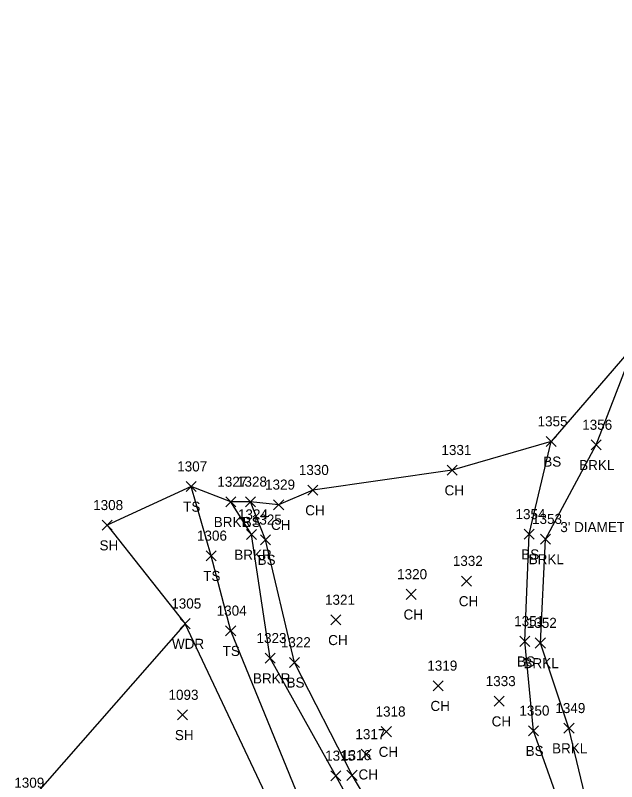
# Model space of a CAD drawing. Extents: x 1651685 to 1653558, y 889533 to 891085.
# Drawn here: x 1652558.4 to 1652677.7, y 890337.8 to 890489.8 of the extents above; entities that cross this region are included whole.
import ezdxf

# ---------------------------------------------------------------- set-up
doc = ezdxf.new("R2010")
doc.units = 0
for name, color, linetype in [('L_A', 7, 'Continuous'), ('L_I', 7, 'Continuous'), ('L_TIC', 7, 'Continuous'), ('LAWA', 7, 'Continuous'), ('LAWE', 7, 'Continuous'), ('LELB', 7, 'Continuous'), ('LSOGP', 7, 'Continuous'), ('U_C', 7, 'Continuous')]:
    doc.layers.add(name, color=color, linetype=linetype)

msp = doc.modelspace()

# ---------------------------------------------------------------- linework, layer by layer
at = {"layer": 'L_TIC'}
for points in [[(1652663.7, 890404.27), (1652665.7, 890406.27)], [(1652665.7, 890404.27), (1652663.7, 890406.27)], [(1652672.62, 890403.58), (1652674.62, 890405.58)], [(1652674.62, 890403.58), (1652672.62, 890405.58)], [(1652644.06, 890398.57), (1652646.06, 890400.57)], [(1652646.06, 890398.57), (1652644.06, 890400.57)], [(1652592.27, 890395.32), (1652594.27, 890397.32)], [(1652594.27, 890395.32), (1652592.27, 890397.32)], [(1652616.41, 890394.61), (1652618.41, 890396.61)], [(1652618.41, 890394.61), (1652616.41, 890396.61)], [(1652600.16, 890392.28), (1652602.16, 890394.28)], [(1652602.16, 890392.28), (1652600.16, 890394.28)], [(1652604.05, 890392.3), (1652606.05, 890394.3)], [(1652606.05, 890392.3), (1652604.05, 890394.3)], [(1652609.63, 890391.71), (1652611.63, 890393.71)], [(1652611.63, 890391.71), (1652609.63, 890393.71)], [(1652575.59, 890387.65), (1652577.59, 890389.65)], [(1652577.59, 890387.65), (1652575.59, 890389.65)], [(1652604.24, 890385.79), (1652606.24, 890387.79)], [(1652606.24, 890385.79), (1652604.24, 890387.79)], [(1652659.32, 890385.85), (1652661.32, 890387.85)], [(1652661.32, 890385.85), (1652659.32, 890387.85)], [(1652607, 890384.77), (1652609, 890386.77)], [(1652609, 890384.77), (1652607, 890386.77)], [(1652662.6, 890384.9), (1652664.6, 890386.9)], [(1652664.6, 890384.9), (1652662.6, 890386.9)], [(1652596.25, 890381.58), (1652598.25, 890383.58)], [(1652598.25, 890381.58), (1652596.25, 890383.58)], [(1652646.89, 890376.57), (1652648.89, 890378.57)], [(1652648.89, 890376.57), (1652646.89, 890378.57)], [(1652635.92, 890373.93), (1652637.92, 890375.93)], [(1652637.92, 890373.93), (1652635.92, 890375.93)], [(1652620.96, 890368.86), (1652622.96, 890370.86)], [(1652622.96, 890368.86), (1652620.96, 890370.86)], [(1652591.1, 890368.11), (1652593.1, 890370.11)], [(1652593.1, 890368.11), (1652591.1, 890370.11)], [(1652600.11, 890366.7), (1652602.11, 890368.7)], [(1652602.11, 890366.7), (1652600.11, 890368.7)], [(1652658.49, 890364.61), (1652660.49, 890366.61)], [(1652660.49, 890364.61), (1652658.49, 890366.61)], [(1652661.56, 890364.27), (1652663.56, 890366.27)], [(1652663.56, 890364.27), (1652661.56, 890366.27)], [(1652607.93, 890361.26), (1652609.93, 890363.26)], [(1652609.93, 890361.26), (1652607.93, 890363.26)], [(1652612.75, 890360.43), (1652614.75, 890362.43)], [(1652614.75, 890360.43), (1652612.75, 890362.43)], [(1652641.26, 890355.79), (1652643.26, 890357.79)], [(1652643.26, 890355.79), (1652641.26, 890357.79)], [(1652653.41, 890352.72), (1652655.41, 890354.72)], [(1652655.41, 890352.72), (1652653.41, 890354.72)], [(1652590.54, 890350), (1652592.54, 890352)], [(1652592.54, 890350), (1652590.54, 890352)], [(1652667.24, 890347.37), (1652669.24, 890349.37)], [(1652669.24, 890347.37), (1652667.24, 890349.37)], [(1652630.99, 890346.68), (1652632.99, 890348.68)], [(1652632.99, 890346.68), (1652630.99, 890348.68)], [(1652660.19, 890346.87), (1652662.19, 890348.87)], [(1652662.19, 890346.87), (1652660.19, 890348.87)], [(1652626.99, 890342.19), (1652628.99, 890344.19)], [(1652628.99, 890342.19), (1652626.99, 890344.19)], [(1652620.98, 890337.92), (1652622.98, 890339.92)], [(1652622.98, 890337.92), (1652620.98, 890339.92)], [(1652624.19, 890338.02), (1652626.19, 890340.02)], [(1652626.19, 890338.02), (1652624.19, 890340.02)]]:
    msp.add_lwpolyline(points, dxfattribs=at)
at = {"layer": 'LAWA'}
msp.add_lwpolyline([(1652634, 890223.2), (1652645.93, 890237.94), (1652644.79, 890250.03), (1652631.58, 890279.12), (1652627.58, 890295.01), (1652615.37, 890319.79), (1652592.1, 890369.11), (1652560.95, 890333.56)], dxfattribs=at)
at = {"layer": 'LAWE'}
for points in [[(1652673.4, 890326.85), (1652668.24, 890348.37), (1652662.56, 890365.27), (1652663.6, 890385.9), (1652673.62, 890404.58), (1652681.39, 890424.61)], [(1652673.03, 890269.95), (1652662.28, 890278.74), (1652652.26, 890288.07), (1652634.07, 890316.8), (1652621.98, 890338.92), (1652608.93, 890362.26), (1652605.24, 890386.79), (1652601.16, 890393.28)]]:
    msp.add_lwpolyline(points, dxfattribs=at)
at = {"layer": 'LELB'}
for points in [[(1652670.46, 890321.8), (1652661.19, 890347.87), (1652659.49, 890365.61), (1652660.32, 890386.85), (1652664.7, 890405.27)], [(1652650.54, 890241.16), (1652659.11, 890253.33), (1652656.31, 890268.79), (1652646.77, 890284.89), (1652637.95, 890297.47), (1652620.82, 890319.5), (1652601.11, 890367.7), (1652597.25, 890382.58), (1652593.27, 890396.32)], [(1652655.64, 890289.65), (1652637.44, 890318.42), (1652625.19, 890339.02), (1652613.75, 890361.43), (1652608, 890385.77), (1652605.05, 890393.3)]]:
    msp.add_lwpolyline(points, dxfattribs=at)
at = {"layer": 'LSOGP'}
msp.add_lwpolyline([(1652755.23, 890514.52), (1652738.16, 890487.37), (1652752.74, 890483.86), (1652743.13, 890454.81), (1652739.83, 890456.16), (1652737.58, 890449.68), (1652732.33, 890451.47), (1652726.97, 890443.32), (1652732.31, 890441.75), (1652729.8, 890435.09), (1652722.88, 890415.78), (1652698.47, 890424.18), (1652681.39, 890424.6), (1652664.7, 890405.27), (1652645.06, 890399.57), (1652617.41, 890395.61), (1652610.62, 890392.71), (1652605.05, 890393.3), (1652601.16, 890393.28), (1652593.27, 890396.32), (1652576.59, 890388.65), (1652592.1, 890369.11), (1652560.95, 890333.56)], dxfattribs=at)

# ---------------------------------------------------------------- texts
at = {"layer": 'L_A'}
for s, p in [('BS', (1652663.14, 890400.27)), ('BRKL', (1652670.26, 890399.58)), ('CH', (1652643.55, 890394.57)), ('TS', (1652591.68, 890391.32)), ('CH', (1652615.9, 890390.61)), ('BRKR', (1652597.75, 890388.28)), ('BS', (1652603.49, 890388.3)), ('CH', (1652609.11, 890387.71)), ('SH', (1652575.08, 890383.65)), ('BRKR', (1652601.83, 890381.79)), ('BS', (1652606.45, 890380.77)), ('BS', (1652658.76, 890381.85)), ('BRKL', (1652660.25, 890380.9)), ('TS', (1652595.66, 890377.58)), ('CH', (1652646.37, 890372.57)), ('CH', (1652635.41, 890369.93)), ('WDR', (1652589.46, 890364.11)), ('CH', (1652620.45, 890364.86)), ('TS', (1652599.51, 890362.7)), ('BS', (1652657.93, 890360.61)), ('BRKL', (1652659.21, 890360.27)), ('BRKR', (1652605.53, 890357.26)), ('BS', (1652612.19, 890356.43)), ('CH', (1652640.75, 890351.79)), ('CH', (1652652.9, 890348.72)), ('SH', (1652590.03, 890346)), ('CH', (1652630.48, 890342.68)), ('BS', (1652659.63, 890342.87)), ('BRKL', (1652664.89, 890343.37)), ('CH', (1652626.47, 890338.19))]:
    msp.add_text(s, height=2, dxfattribs=at).set_placement(p)
at = {"layer": 'L_I'}
for s, p in [('1355', (1652662.01, 890408.27)), ('1356', (1652670.87, 890407.58)), ('1331', (1652642.93, 890402.57)), ('1307', (1652590.5, 890399.32)), ('1330', (1652614.63, 890398.61)), ('1327', (1652598.46, 890396.28)), ('1328', (1652602.36, 890396.3)), ('1329', (1652607.93, 890395.71)), ('1308', (1652573.82, 890391.65)), ('1324', (1652602.55, 890389.79)), ('1354', (1652657.63, 890389.85)), ('1325', (1652605.31, 890388.77)), ('1353', (1652660.91, 890388.9)), ('1306', (1652594.42, 890385.58)), ('1332', (1652645.19, 890380.57)), ('1320', (1652634.14, 890377.93)), ('1305', (1652589.32, 890372.11)), ('1321', (1652619.83, 890372.86)), ('1304', (1652598.33, 890370.7)), ('1351', (1652657.36, 890368.61)), ('1352', (1652659.87, 890368.27)), ('1323', (1652606.24, 890365.26)), ('1322', (1652611.06, 890364.43)), ('1319', (1652640.13, 890359.79)), ('1333', (1652651.72, 890356.72)), ('1093', (1652588.77, 890354)), ('1318', (1652629.86, 890350.68)), ('1350', (1652658.41, 890350.87)), ('1349', (1652665.54, 890351.37)), ('1317', (1652625.86, 890346.19)), ('1315', (1652619.85, 890341.92)), ('1316', (1652623.01, 890342.02)), ('1309', (1652558.17, 890336.56))]:
    msp.add_text(s, height=2, dxfattribs=at).set_placement(p)
at = {"layer": 'U_C'}
msp.add_text("3' DIAMETER CONCRETE TILE", height=2, dxfattribs=at).set_placement((1652666.52, 890387.28))

doc.saveas('drawing.dxf')
